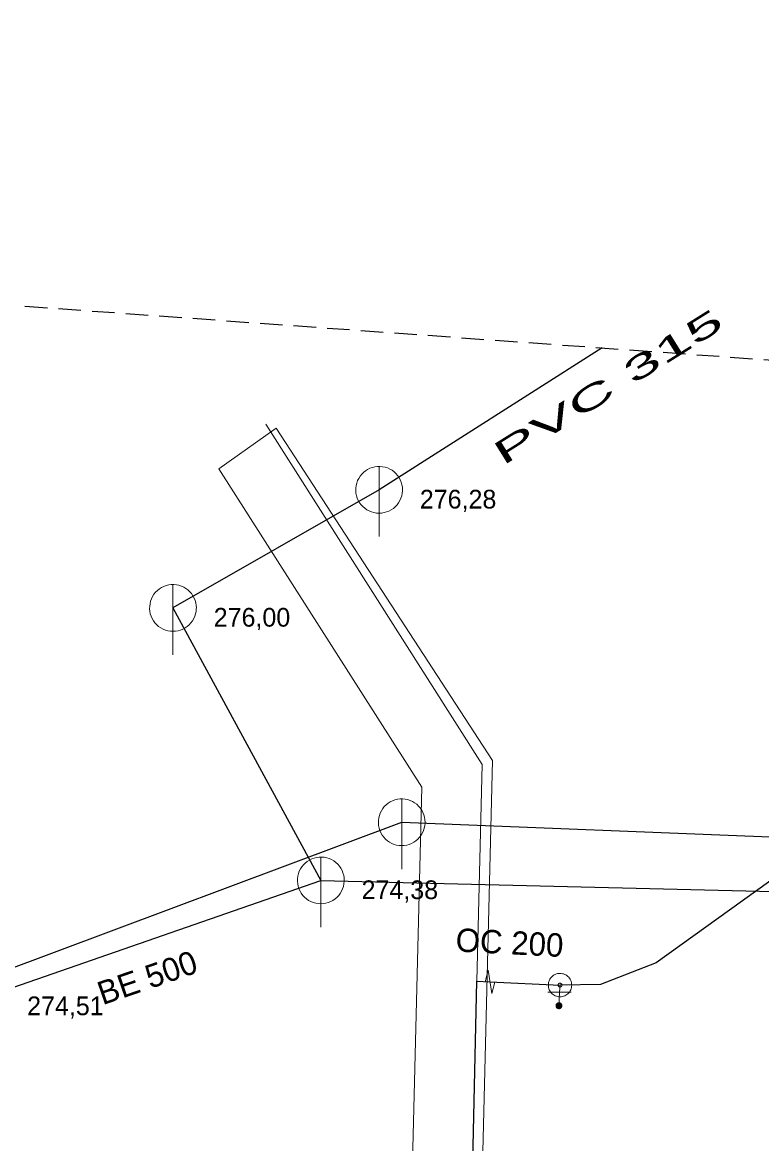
# Model space of a CAD drawing. Extents: x -725153 to -724843, y -978146 to -977794.
# Drawn here: x -724958.1 to -724926.5, y -977842.4 to -977794.45 of the extents above; entities that cross this region are included whole.
import ezdxf

# ---------------------------------------------------------------- set-up
doc = ezdxf.new("R2010")
doc.units = 0
doc.header["$LTSCALE"] = 0.32
doc.linetypes.add('MEDIUM_DASHED', pattern=[4.5, 3, -1.5])
doc.layers.add('1', color=7, linetype='Continuous')
for name, color, linetype, lineweight in [('13', 7, 'Continuous', 13), ('14', 7, 'Continuous', 25), ('17', 7, 'Continuous', 25), ('2', 7, 'Continuous', 13), ('22', 7, 'Continuous', 13), ('34', 7, 'Continuous', 13), ('47', 7, 'Continuous', 13), ('63', 7, 'MEDIUM_DASHED', 25), ('9', 7, 'Continuous', 13)]:
    doc.layers.add(name, color=color, linetype=linetype, lineweight=lineweight)

msp = doc.modelspace()

# ---------------------------------------------------------------- linework, layer by layer
at = {"layer": '13'}
msp.add_lwpolyline([(-724938.671, -977835.461), (-724938.448, -977826.182), (-724947.693, -977811.627)], dxfattribs=at)
at = {"layer": '14'}
for p, q in [((-724933.308, -977808.37), (-724942.853, -977814.441)), ((-724942.853, -977814.441), (-724951.666, -977819.491)), ((-724951.666, -977819.491), (-724945.344, -977831.146)), ((-724983.75, -977844.32), (-724941.885, -977828.658)), ((-724941.885, -977828.658), (-724896.642, -977830.439)), ((-724959.646, -977836.111), (-724945.344, -977831.146)), ((-724945.344, -977831.146), (-724888.89, -977832.52))]:
    msp.add_line(p, q, dxfattribs=at)
at = {"layer": '14', "lineweight": 13}
for p, q in [((-724935.115, -977835.623), (-724935.135, -977835.927)), ((-724935.135, -977835.927), (-724935.16, -977836.505))]:
    msp.add_line(p, q, dxfattribs=at)
at = {"layer": '17'}
msp.add_line((-724938.11, -977835.486), (-724935.115, -977835.623), dxfattribs=at)
for points in [[(-724897.93, -977810.925), (-724931.009, -977834.677), (-724933.379, -977835.594), (-724935.115, -977835.623)], [(-724932.296, -977965.921), (-724930.809, -977903.881), (-724940.261, -977903.85), (-724939.557, -977875.228), (-724938.671, -977835.46), (-724938.11, -977835.486)]]:
    msp.add_lwpolyline(points, dxfattribs=at)
at = {"layer": '2'}
msp.add_lwpolyline([(-724949.699, -977813.541), (-724947.256, -977811.8), (-724938.004, -977826.019), (-724939.917, -977903.34), (-724930.427, -977903.434), (-724931.995, -977966.488), (-724934.98, -977966.357), (-724933.489, -977906.375), (-724942.987, -977906.14), (-724941.021, -977827.164)], close=True, dxfattribs=at)
at = {"layer": '22'}
for p, q in [((-724942.853, -977816.441), (-724942.852, -977813.441)), ((-724951.667, -977821.492), (-724951.666, -977818.492)), ((-724941.885, -977830.658), (-724941.884, -977827.658)), ((-724945.344, -977833.146), (-724945.343, -977830.146))]:
    msp.add_line(p, q, dxfattribs=at)
for points in [[(-724941.853, -977814.441), (-724941.858, -977814.332), (-724941.876, -977814.224), (-724941.906, -977814.118), (-724941.946, -977814.017), (-724941.998, -977813.92), (-724942.06, -977813.83), (-724942.132, -977813.747), (-724942.212, -977813.673), (-724942.3, -977813.607), (-724942.394, -977813.552), (-724942.494, -977813.507), (-724942.599, -977813.474), (-724942.706, -977813.452), (-724942.815, -977813.442), (-724942.925, -977813.444), (-724943.033, -977813.458), (-724943.14, -977813.483), (-724943.243, -977813.52), (-724943.341, -977813.569), (-724943.433, -977813.627), (-724943.519, -977813.696), (-724943.596, -977813.773), (-724943.665, -977813.859), (-724943.724, -977813.951), (-724943.772, -977814.049), (-724943.809, -977814.152), (-724943.835, -977814.259), (-724943.849, -977814.367), (-724943.852, -977814.477), (-724943.842, -977814.586), (-724943.821, -977814.693), (-724943.787, -977814.797), (-724943.743, -977814.897), (-724943.688, -977814.992), (-724943.622, -977815.08), (-724943.548, -977815.16), (-724943.465, -977815.232), (-724943.375, -977815.294), (-724943.279, -977815.346), (-724943.177, -977815.387), (-724943.072, -977815.417), (-724942.964, -977815.435), (-724942.854, -977815.441), (-724942.745, -977815.435), (-724942.637, -977815.417), (-724942.532, -977815.388), (-724942.43, -977815.347), (-724942.333, -977815.295), (-724942.243, -977815.233), (-724942.16, -977815.162), (-724942.085, -977815.082), (-724942.02, -977814.994), (-724941.964, -977814.9), (-724941.92, -977814.8), (-724941.886, -977814.696), (-724941.864, -977814.588), (-724941.854, -977814.479)], [(-724950.667, -977819.492), (-724950.672, -977819.383), (-724950.69, -977819.275), (-724950.72, -977819.169), (-724950.76, -977819.068), (-724950.812, -977818.971), (-724950.874, -977818.881), (-724950.946, -977818.798), (-724951.026, -977818.724), (-724951.114, -977818.658), (-724951.208, -977818.603), (-724951.308, -977818.558), (-724951.413, -977818.525), (-724951.52, -977818.503), (-724951.629, -977818.493), (-724951.739, -977818.495), (-724951.847, -977818.509), (-724951.954, -977818.534), (-724952.057, -977818.571), (-724952.155, -977818.62), (-724952.247, -977818.678), (-724952.333, -977818.747), (-724952.41, -977818.824), (-724952.479, -977818.91), (-724952.538, -977819.002), (-724952.586, -977819.1), (-724952.623, -977819.203), (-724952.649, -977819.31), (-724952.663, -977819.418), (-724952.666, -977819.528), (-724952.656, -977819.637), (-724952.635, -977819.744), (-724952.601, -977819.848), (-724952.557, -977819.948), (-724952.502, -977820.043), (-724952.436, -977820.131), (-724952.362, -977820.211), (-724952.279, -977820.283), (-724952.189, -977820.345), (-724952.093, -977820.397), (-724951.991, -977820.438), (-724951.886, -977820.468), (-724951.778, -977820.486), (-724951.668, -977820.492), (-724951.559, -977820.486), (-724951.451, -977820.468), (-724951.346, -977820.439), (-724951.244, -977820.398), (-724951.147, -977820.346), (-724951.057, -977820.284), (-724950.974, -977820.213), (-724950.899, -977820.133), (-724950.834, -977820.045), (-724950.778, -977819.951), (-724950.734, -977819.851), (-724950.7, -977819.747), (-724950.678, -977819.639), (-724950.668, -977819.53)], [(-724940.885, -977828.658), (-724940.89, -977828.549), (-724940.908, -977828.441), (-724940.938, -977828.335), (-724940.978, -977828.234), (-724941.03, -977828.137), (-724941.092, -977828.047), (-724941.164, -977827.964), (-724941.244, -977827.89), (-724941.332, -977827.824), (-724941.426, -977827.769), (-724941.526, -977827.724), (-724941.631, -977827.691), (-724941.738, -977827.669), (-724941.847, -977827.659), (-724941.957, -977827.661), (-724942.065, -977827.675), (-724942.172, -977827.7), (-724942.275, -977827.737), (-724942.373, -977827.786), (-724942.465, -977827.844), (-724942.551, -977827.913), (-724942.628, -977827.99), (-724942.697, -977828.076), (-724942.756, -977828.168), (-724942.804, -977828.266), (-724942.841, -977828.369), (-724942.867, -977828.476), (-724942.881, -977828.584), (-724942.884, -977828.694), (-724942.874, -977828.803), (-724942.853, -977828.91), (-724942.819, -977829.014), (-724942.775, -977829.114), (-724942.72, -977829.209), (-724942.654, -977829.297), (-724942.58, -977829.377), (-724942.497, -977829.449), (-724942.407, -977829.511), (-724942.311, -977829.563), (-724942.209, -977829.604), (-724942.104, -977829.634), (-724941.996, -977829.652), (-724941.886, -977829.658), (-724941.777, -977829.652), (-724941.669, -977829.634), (-724941.564, -977829.605), (-724941.462, -977829.564), (-724941.365, -977829.512), (-724941.275, -977829.45), (-724941.192, -977829.379), (-724941.117, -977829.299), (-724941.052, -977829.211), (-724940.996, -977829.117), (-724940.952, -977829.017), (-724940.918, -977828.913), (-724940.896, -977828.805), (-724940.886, -977828.696)], [(-724944.344, -977831.146), (-724944.349, -977831.037), (-724944.367, -977830.929), (-724944.397, -977830.823), (-724944.437, -977830.722), (-724944.489, -977830.625), (-724944.551, -977830.535), (-724944.623, -977830.452), (-724944.703, -977830.378), (-724944.791, -977830.312), (-724944.885, -977830.257), (-724944.985, -977830.212), (-724945.09, -977830.179), (-724945.197, -977830.157), (-724945.306, -977830.147), (-724945.416, -977830.149), (-724945.524, -977830.163), (-724945.631, -977830.188), (-724945.734, -977830.225), (-724945.832, -977830.274), (-724945.924, -977830.332), (-724946.01, -977830.401), (-724946.087, -977830.478), (-724946.156, -977830.564), (-724946.215, -977830.656), (-724946.263, -977830.754), (-724946.3, -977830.857), (-724946.326, -977830.964), (-724946.34, -977831.072), (-724946.343, -977831.182), (-724946.333, -977831.291), (-724946.312, -977831.398), (-724946.278, -977831.502), (-724946.234, -977831.602), (-724946.179, -977831.697), (-724946.113, -977831.785), (-724946.039, -977831.865), (-724945.956, -977831.937), (-724945.866, -977831.999), (-724945.77, -977832.051), (-724945.668, -977832.092), (-724945.563, -977832.122), (-724945.455, -977832.14), (-724945.345, -977832.146), (-724945.236, -977832.14), (-724945.128, -977832.122), (-724945.023, -977832.093), (-724944.921, -977832.052), (-724944.824, -977832), (-724944.734, -977831.938), (-724944.651, -977831.867), (-724944.576, -977831.787), (-724944.511, -977831.699), (-724944.455, -977831.605), (-724944.411, -977831.505), (-724944.377, -977831.401), (-724944.355, -977831.293), (-724944.345, -977831.184)]]:
    msp.add_lwpolyline(points, close=True, dxfattribs=at)
at = {"layer": '34'}
msp.add_line((-724935.635, -977835.926), (-724934.635, -977835.928), dxfattribs=at)
at = {"layer": '47'}
msp.add_line((-724938.191, -977834.983), (-724938.31, -977835.479), dxfattribs=at)
msp.add_lwpolyline([(-724938.191, -977834.983), (-724938.028, -977835.988), (-724937.909, -977835.492)], dxfattribs=at)
for points in [[(-724934.615, -977835.624), (-724934.617, -977835.572), (-724934.625, -977835.52), (-724934.639, -977835.47), (-724934.657, -977835.421), (-724934.681, -977835.374), (-724934.71, -977835.33), (-724934.743, -977835.289), (-724934.78, -977835.252), (-724934.819, -977835.219), (-724934.863, -977835.19), (-724934.91, -977835.166), (-724934.959, -977835.148), (-724935.009, -977835.134), (-724935.061, -977835.126), (-724935.113, -977835.123), (-724935.165, -977835.125), (-724935.217, -977835.133), (-724935.268, -977835.147), (-724935.316, -977835.165), (-724935.363, -977835.189), (-724935.407, -977835.218), (-724935.449, -977835.251), (-724935.486, -977835.288), (-724935.519, -977835.327), (-724935.547, -977835.371), (-724935.571, -977835.418), (-724935.59, -977835.467), (-724935.603, -977835.517), (-724935.611, -977835.569), (-724935.614, -977835.621), (-724935.612, -977835.673), (-724935.604, -977835.725), (-724935.591, -977835.776), (-724935.572, -977835.824), (-724935.548, -977835.871), (-724935.52, -977835.915), (-724935.487, -977835.957), (-724935.45, -977835.994), (-724935.41, -977836.027), (-724935.366, -977836.055), (-724935.319, -977836.079), (-724935.271, -977836.098), (-724935.22, -977836.111), (-724935.168, -977836.119), (-724935.116, -977836.122), (-724935.064, -977836.12), (-724935.012, -977836.112), (-724934.962, -977836.099), (-724934.913, -977836.08), (-724934.866, -977836.056), (-724934.822, -977836.028), (-724934.781, -977835.995), (-724934.744, -977835.958), (-724934.711, -977835.918), (-724934.682, -977835.874), (-724934.658, -977835.827), (-724934.64, -977835.779), (-724934.626, -977835.728), (-724934.618, -977835.676)], [(-724935.033, -977835.623), (-724935.032, -977835.614), (-724935.034, -977835.606), (-724935.036, -977835.598), (-724935.039, -977835.59), (-724935.043, -977835.582), (-724935.048, -977835.575), (-724935.053, -977835.568), (-724935.059, -977835.562), (-724935.066, -977835.557), (-724935.073, -977835.552), (-724935.081, -977835.548), (-724935.089, -977835.545), (-724935.097, -977835.543), (-724935.105, -977835.541), (-724935.114, -977835.541), (-724935.123, -977835.54), (-724935.131, -977835.542), (-724935.139, -977835.544), (-724935.147, -977835.547), (-724935.155, -977835.551), (-724935.162, -977835.556), (-724935.169, -977835.561), (-724935.175, -977835.567), (-724935.181, -977835.574), (-724935.185, -977835.581), (-724935.189, -977835.589), (-724935.192, -977835.597), (-724935.194, -977835.605), (-724935.196, -977835.613), (-724935.196, -977835.622), (-724935.197, -977835.631), (-724935.195, -977835.639), (-724935.193, -977835.647), (-724935.19, -977835.655), (-724935.186, -977835.663), (-724935.182, -977835.67), (-724935.176, -977835.677), (-724935.17, -977835.683), (-724935.163, -977835.689), (-724935.156, -977835.693), (-724935.148, -977835.697), (-724935.14, -977835.7), (-724935.132, -977835.702), (-724935.124, -977835.704), (-724935.115, -977835.704), (-724935.106, -977835.705), (-724935.098, -977835.703), (-724935.09, -977835.701), (-724935.082, -977835.698), (-724935.074, -977835.694), (-724935.067, -977835.69), (-724935.06, -977835.684), (-724935.054, -977835.678), (-724935.049, -977835.671), (-724935.044, -977835.664), (-724935.04, -977835.656), (-724935.037, -977835.648), (-724935.035, -977835.64), (-724935.033, -977835.632)]]:
    msp.add_lwpolyline(points, close=True, dxfattribs=at)
at = {"layer": '63'}
msp.add_lwpolyline([(-725126.038, -977904.704), (-725126.038, -977794.451), (-724874.829, -977812.594), (-724855.29, -977827.945), (-724842.73, -977919.358), (-724859.477, -977998.21), (-724911.114, -978092.413), (-724961.356, -978146.144), (-725152.554, -978126.605)], close=True, dxfattribs=at)
at = {"layer": '9'}
for points in [[(-724935.286, -977836.505), (-724935.286, -977836.518), (-724935.284, -977836.531), (-724935.281, -977836.544), (-724935.276, -977836.556), (-724935.27, -977836.568), (-724935.263, -977836.579), (-724935.255, -977836.589), (-724935.245, -977836.599), (-724935.235, -977836.607), (-724935.224, -977836.614), (-724935.212, -977836.62), (-724935.2, -977836.625), (-724935.187, -977836.628), (-724935.174, -977836.63), (-724935.161, -977836.632), (-724935.148, -977836.631), (-724935.135, -977836.629), (-724935.122, -977836.626), (-724935.11, -977836.621), (-724935.098, -977836.615), (-724935.087, -977836.608), (-724935.077, -977836.6), (-724935.067, -977836.59), (-724935.059, -977836.58), (-724935.052, -977836.569), (-724935.046, -977836.557), (-724935.041, -977836.545), (-724935.038, -977836.532), (-724935.036, -977836.519), (-724935.034, -977836.506), (-724935.035, -977836.493), (-724935.037, -977836.48), (-724935.04, -977836.467), (-724935.045, -977836.455), (-724935.051, -977836.443), (-724935.058, -977836.432), (-724935.066, -977836.422), (-724935.076, -977836.412), (-724935.086, -977836.404), (-724935.097, -977836.397), (-724935.109, -977836.391), (-724935.121, -977836.386), (-724935.134, -977836.383), (-724935.147, -977836.381), (-724935.16, -977836.38), (-724935.173, -977836.38), (-724935.186, -977836.382), (-724935.199, -977836.385), (-724935.211, -977836.39), (-724935.223, -977836.396), (-724935.234, -977836.403), (-724935.244, -977836.411), (-724935.254, -977836.421), (-724935.262, -977836.431), (-724935.269, -977836.442), (-724935.275, -977836.454), (-724935.28, -977836.466), (-724935.283, -977836.479), (-724935.285, -977836.492)], [(-724935.266, -977836.505), (-724935.267, -977836.516), (-724935.265, -977836.527), (-724935.262, -977836.538), (-724935.258, -977836.548), (-724935.253, -977836.558), (-724935.247, -977836.567), (-724935.24, -977836.576), (-724935.232, -977836.584), (-724935.223, -977836.591), (-724935.214, -977836.597), (-724935.204, -977836.602), (-724935.194, -977836.606), (-724935.183, -977836.609), (-724935.172, -977836.612), (-724935.161, -977836.612), (-724935.15, -977836.612), (-724935.139, -977836.61), (-724935.128, -977836.607), (-724935.118, -977836.603), (-724935.108, -977836.598), (-724935.099, -977836.592), (-724935.09, -977836.585), (-724935.082, -977836.577), (-724935.075, -977836.568), (-724935.069, -977836.559), (-724935.064, -977836.549), (-724935.06, -977836.539), (-724935.057, -977836.528), (-724935.055, -977836.517), (-724935.054, -977836.506), (-724935.054, -977836.495), (-724935.056, -977836.484), (-724935.059, -977836.473), (-724935.063, -977836.463), (-724935.068, -977836.453), (-724935.074, -977836.444), (-724935.081, -977836.435), (-724935.089, -977836.427), (-724935.098, -977836.42), (-724935.107, -977836.414), (-724935.117, -977836.409), (-724935.127, -977836.405), (-724935.138, -977836.402), (-724935.149, -977836.4), (-724935.16, -977836.4), (-724935.171, -977836.399), (-724935.182, -977836.401), (-724935.193, -977836.404), (-724935.203, -977836.408), (-724935.213, -977836.413), (-724935.222, -977836.419), (-724935.231, -977836.426), (-724935.239, -977836.434), (-724935.246, -977836.443), (-724935.252, -977836.452), (-724935.257, -977836.462), (-724935.261, -977836.472), (-724935.264, -977836.483), (-724935.266, -977836.494)], [(-724935.247, -977836.505), (-724935.247, -977836.514), (-724935.246, -977836.523), (-724935.243, -977836.532), (-724935.24, -977836.54), (-724935.236, -977836.548), (-724935.231, -977836.556), (-724935.225, -977836.563), (-724935.219, -977836.569), (-724935.212, -977836.575), (-724935.204, -977836.58), (-724935.196, -977836.584), (-724935.188, -977836.587), (-724935.179, -977836.59), (-724935.17, -977836.591), (-724935.161, -977836.593), (-724935.152, -977836.592), (-724935.143, -977836.591), (-724935.134, -977836.588), (-724935.126, -977836.585), (-724935.118, -977836.581), (-724935.11, -977836.576), (-724935.103, -977836.57), (-724935.097, -977836.564), (-724935.091, -977836.557), (-724935.086, -977836.549), (-724935.082, -977836.541), (-724935.079, -977836.533), (-724935.076, -977836.524), (-724935.075, -977836.515), (-724935.073, -977836.506), (-724935.074, -977836.497), (-724935.075, -977836.488), (-724935.078, -977836.479), (-724935.081, -977836.471), (-724935.085, -977836.463), (-724935.09, -977836.455), (-724935.096, -977836.448), (-724935.102, -977836.442), (-724935.109, -977836.436), (-724935.117, -977836.431), (-724935.125, -977836.427), (-724935.133, -977836.424), (-724935.142, -977836.421), (-724935.151, -977836.42), (-724935.16, -977836.419), (-724935.169, -977836.419), (-724935.178, -977836.42), (-724935.187, -977836.423), (-724935.195, -977836.426), (-724935.203, -977836.43), (-724935.211, -977836.435), (-724935.218, -977836.441), (-724935.224, -977836.447), (-724935.23, -977836.454), (-724935.235, -977836.462), (-724935.239, -977836.47), (-724935.242, -977836.478), (-724935.245, -977836.487), (-724935.246, -977836.496)], [(-724935.227, -977836.505), (-724935.227, -977836.512), (-724935.226, -977836.519), (-724935.225, -977836.526), (-724935.222, -977836.532), (-724935.219, -977836.538), (-724935.215, -977836.544), (-724935.211, -977836.55), (-724935.206, -977836.555), (-724935.2, -977836.559), (-724935.194, -977836.563), (-724935.188, -977836.566), (-724935.182, -977836.569), (-724935.175, -977836.57), (-724935.168, -977836.573), (-724935.161, -977836.573), (-724935.154, -977836.573), (-724935.147, -977836.571), (-724935.14, -977836.57), (-724935.134, -977836.567), (-724935.127, -977836.564), (-724935.122, -977836.56), (-724935.116, -977836.556), (-724935.111, -977836.551), (-724935.107, -977836.545), (-724935.103, -977836.539), (-724935.1, -977836.533), (-724935.097, -977836.527), (-724935.095, -977836.52), (-724935.094, -977836.513), (-724935.093, -977836.506), (-724935.093, -977836.499), (-724935.094, -977836.492), (-724935.096, -977836.485), (-724935.099, -977836.479), (-724935.102, -977836.472), (-724935.106, -977836.467), (-724935.11, -977836.461), (-724935.115, -977836.456), (-724935.121, -977836.452), (-724935.126, -977836.448), (-724935.133, -977836.445), (-724935.139, -977836.442), (-724935.146, -977836.44), (-724935.153, -977836.439), (-724935.16, -977836.439), (-724935.167, -977836.439), (-724935.174, -977836.439), (-724935.181, -977836.441), (-724935.187, -977836.444), (-724935.193, -977836.447), (-724935.199, -977836.451), (-724935.205, -977836.455), (-724935.21, -977836.46), (-724935.214, -977836.466), (-724935.218, -977836.471), (-724935.221, -977836.478), (-724935.224, -977836.484), (-724935.225, -977836.491), (-724935.227, -977836.498)], [(-724935.207, -977836.505), (-724935.207, -977836.51), (-724935.207, -977836.515), (-724935.206, -977836.52), (-724935.204, -977836.524), (-724935.202, -977836.529), (-724935.199, -977836.533), (-724935.196, -977836.536), (-724935.192, -977836.54), (-724935.189, -977836.543), (-724935.185, -977836.546), (-724935.18, -977836.548), (-724935.176, -977836.55), (-724935.171, -977836.551), (-724935.166, -977836.553), (-724935.161, -977836.553), (-724935.156, -977836.553), (-724935.151, -977836.552), (-724935.146, -977836.551), (-724935.142, -977836.549), (-724935.137, -977836.547), (-724935.133, -977836.544), (-724935.129, -977836.541), (-724935.126, -977836.537), (-724935.123, -977836.534), (-724935.12, -977836.53), (-724935.118, -977836.525), (-724935.116, -977836.521), (-724935.115, -977836.516), (-724935.114, -977836.511), (-724935.113, -977836.506), (-724935.113, -977836.501), (-724935.114, -977836.496), (-724935.115, -977836.491), (-724935.117, -977836.487), (-724935.119, -977836.482), (-724935.122, -977836.478), (-724935.125, -977836.474), (-724935.128, -977836.471), (-724935.132, -977836.468), (-724935.136, -977836.465), (-724935.141, -977836.463), (-724935.145, -977836.461), (-724935.15, -977836.46), (-724935.155, -977836.459), (-724935.16, -977836.459), (-724935.165, -977836.459), (-724935.17, -977836.46), (-724935.175, -977836.46), (-724935.179, -977836.462), (-724935.184, -977836.464), (-724935.188, -977836.467), (-724935.191, -977836.47), (-724935.195, -977836.473), (-724935.198, -977836.477), (-724935.201, -977836.481), (-724935.203, -977836.486), (-724935.205, -977836.49), (-724935.206, -977836.495), (-724935.207, -977836.5)], [(-724935.187, -977836.505), (-724935.187, -977836.508), (-724935.188, -977836.511), (-724935.187, -977836.513), (-724935.186, -977836.516), (-724935.185, -977836.519), (-724935.183, -977836.521), (-724935.181, -977836.523), (-724935.179, -977836.525), (-724935.177, -977836.527), (-724935.175, -977836.529), (-724935.172, -977836.531), (-724935.169, -977836.532), (-724935.167, -977836.532), (-724935.164, -977836.533), (-724935.161, -977836.533), (-724935.158, -977836.533), (-724935.155, -977836.533), (-724935.152, -977836.532), (-724935.15, -977836.531), (-724935.147, -977836.53), (-724935.145, -977836.528), (-724935.142, -977836.526), (-724935.14, -977836.524), (-724935.139, -977836.522), (-724935.137, -977836.52), (-724935.136, -977836.517), (-724935.134, -977836.514), (-724935.134, -977836.512), (-724935.133, -977836.509), (-724935.132, -977836.506), (-724935.133, -977836.503), (-724935.133, -977836.5), (-724935.134, -977836.497), (-724935.135, -977836.495), (-724935.136, -977836.492), (-724935.138, -977836.49), (-724935.139, -977836.487), (-724935.141, -977836.485), (-724935.144, -977836.484), (-724935.146, -977836.482), (-724935.149, -977836.481), (-724935.151, -977836.48), (-724935.154, -977836.479), (-724935.157, -977836.479), (-724935.16, -977836.478), (-724935.163, -977836.479), (-724935.166, -977836.478), (-724935.168, -977836.48), (-724935.171, -977836.48), (-724935.174, -977836.481), (-724935.176, -977836.483), (-724935.178, -977836.484), (-724935.18, -977836.486), (-724935.182, -977836.489), (-724935.184, -977836.491), (-724935.185, -977836.494), (-724935.186, -977836.496), (-724935.187, -977836.499), (-724935.187, -977836.502)], [(-724935.168, -977836.505), (-724935.168, -977836.507), (-724935.168, -977836.507), (-724935.167, -977836.507), (-724935.167, -977836.509), (-724935.168, -977836.51), (-724935.166, -977836.51), (-724935.166, -977836.51), (-724935.166, -977836.512), (-724935.166, -977836.512), (-724935.165, -977836.513), (-724935.163, -977836.513), (-724935.163, -977836.513), (-724935.163, -977836.514), (-724935.161, -977836.514), (-724935.161, -977836.514), (-724935.16, -977836.514), (-724935.159, -977836.514), (-724935.159, -977836.513), (-724935.158, -977836.513), (-724935.156, -977836.513), (-724935.156, -977836.512), (-724935.156, -977836.512), (-724935.155, -977836.511), (-724935.155, -977836.511), (-724935.153, -977836.51), (-724935.153, -977836.509), (-724935.152, -977836.508), (-724935.152, -977836.508), (-724935.152, -977836.507), (-724935.152, -977836.506), (-724935.152, -977836.505), (-724935.152, -977836.504), (-724935.152, -977836.504), (-724935.153, -977836.503), (-724935.153, -977836.502), (-724935.154, -977836.501), (-724935.154, -977836.501), (-724935.155, -977836.5), (-724935.155, -977836.5), (-724935.156, -977836.499), (-724935.157, -977836.499), (-724935.158, -977836.498), (-724935.158, -977836.498), (-724935.159, -977836.498), (-724935.16, -977836.498), (-724935.161, -977836.498), (-724935.162, -977836.498), (-724935.162, -977836.498), (-724935.163, -977836.499), (-724935.164, -977836.498), (-724935.165, -977836.5), (-724935.165, -977836.5), (-724935.166, -977836.5), (-724935.166, -977836.5), (-724935.167, -977836.502), (-724935.167, -977836.503), (-724935.167, -977836.504), (-724935.168, -977836.504), (-724935.168, -977836.505)]]:
    msp.add_lwpolyline(points, close=True, dxfattribs=at)

# ---------------------------------------------------------------- texts
at = {"layer": '1', "width": 2.1}
msp.add_text('PVC 315 ', height=1, rotation=32, dxfattribs=at).set_placement((-724937.565, -977813.431))
at = {"layer": '1'}
for s, rotation, p in [('OC 200', 357, (-724939.598, -977834.183)), ('BE 500', 19, (-724954.677, -977836.487))]:
    msp.add_text(s, height=1, rotation=rotation, dxfattribs=at).set_placement(p)
at = {"layer": '22'}
for s, p in [('276,28', (-724941.11, -977815.24)), ('276,00', (-724949.924, -977820.292)), ('274,38', (-724943.601, -977831.945)), ('274,51', (-724957.903, -977836.91))]:
    msp.add_text(s, height=0.8, dxfattribs=at).set_placement(p)

doc.saveas('drawing.dxf')
